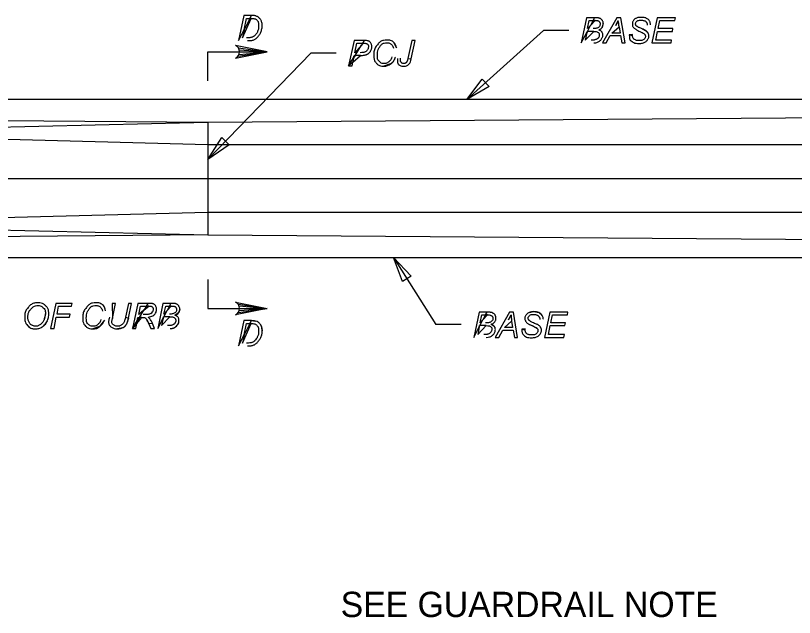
# Model space of a CAD drawing. Extents: x 0 to 680, y 0 to 440.
# Drawn here: x 153 to 239.1, y 317.2 to 383.8 of the extents above; entities that cross this region are included whole.
import ezdxf

# ---------------------------------------------------------------- set-up
doc = ezdxf.new("R2010")
doc.units = 0
doc.layers.add('Default', color=7, linetype='Continuous')

msp = doc.modelspace()

# ---------------------------------------------------------------- linework, layer by layer
at = {"layer": 'Default'}
for p, q in [((217.983, 382.884), (217.844, 382.468)), ((219.368, 382.662), (219.645, 383.244)), ((202.881, 374.488), (211.36, 382.136)), ((214.159, 382.136), (211.36, 382.136)), ((222.278, 382.302), (222.693, 382.081)), ((222.693, 382.081), (222.943, 381.831)), ((177.61, 380.224), (180.796, 379.781)), ((177.72, 380.002), (180.796, 379.781)), ((194.79, 380.834), (195.094, 380.196)), ((174.229, 379.781), (180.796, 379.781)), ((174.229, 376.566), (174.229, 379.781)), ((174.229, 367.865), (185.618, 379.614)), ((177.582, 379.282), (180.796, 379.781)), ((177.693, 379.476), (180.796, 379.781)), ((177.748, 379.781), (180.796, 379.781)), ((188.416, 379.614), (185.618, 379.614)), ((194.457, 378.423), (193.709, 378.173)), ((194.762, 357.031), (199.473, 349.605)), ((174.229, 354.592), (174.229, 351.378)), ((177.582, 351.877), (180.796, 351.378)), ((177.693, 351.683), (180.796, 351.378)), ((156.273, 350.796), (156.162, 350.27)), ((168.105, 351.018), (167.911, 350.824)), ((170.987, 350.907), (170.599, 350.63)), ((171.125, 351.323), (170.987, 350.907)), ((174.229, 351.378), (180.796, 351.378)), ((177.61, 350.935), (180.796, 351.378)), ((177.72, 351.156), (180.796, 351.378)), ((177.748, 351.378), (180.796, 351.378)), ((209.781, 350.962), (210.307, 351.046)), ((210.307, 351.046), (210.861, 350.935)), ((210.861, 350.935), (211.221, 350.63)), ((156.467, 350.02), (156.162, 349.577)), ((162.785, 350.103), (162.258, 349.383)), ((165.473, 350.325), (165.251, 349.66)), ((167.468, 350.187), (167.717, 349.688)), ((179.05, 350.048), (179.522, 349.993)), ((207.481, 350.131), (207.785, 350.685)), ((154.527, 349.3), (154.112, 349.743)), ((162.258, 349.383), (161.51, 349.134)), ((164.835, 349.272), (164.253, 349.134)), ((170.904, 349.632), (170.571, 349.3)), ((180.159, 349.411), (180.242, 348.912)), ((202.271, 349.605), (199.473, 349.605)), ((205.596, 349.66), (205.929, 349.438)), ((210.141, 349.466), (210.667, 349.189)), ((205.596, 348.829), (205.402, 348.635)), ((179.522, 347.942), (179.3, 347.72))]:
    msp.add_line(p, q, dxfattribs=at)
for points in [[(178.895, 383.466), (179.05, 383.771), (178.219, 383.771), (177.637, 381), (178.247, 382.196), (178.524, 383.466)], [(178.895, 383.466), (178.247, 382.196), (178.053, 381.305), (179.023, 383.466)], [(216.22, 382.025), (216.569, 382.684), (216.237, 382.33), (216.431, 383.217), (216.851, 383.217), (217.013, 383.521), (216.126, 383.521), (215.544, 380.75), (216.158, 381.909), (216.182, 382.025)], [(217.9, 380.75), (218.315, 380.75), (218.759, 381.554), (219.895, 381.554), (220.033, 380.75), (220.393, 380.75), (219.922, 383.521), (219.479, 383.521)], [(223.358, 380.75), (225.492, 380.75), (225.547, 381.055), (223.802, 381.055), (223.996, 382.025), (225.631, 382.025), (225.686, 382.358), (224.051, 382.358), (224.245, 383.217), (225.908, 383.217), (225.963, 383.521), (223.94, 383.521)], [(216.569, 382.684), (217.068, 383.217), (216.851, 383.217)], [(216.22, 382.025), (216.158, 381.909), (215.988, 381.055), (216.93, 382.025)], [(190.522, 379.365), (191.25, 380.514), (190.495, 379.67), (190.716, 380.723), (191.382, 380.723), (191.575, 381.028), (190.411, 381.028), (189.802, 378.229), (190.362, 379.113), (190.411, 379.365)], [(196.729, 378.977), (197.173, 381.028), (196.785, 381.028), (196.369, 379.032)], [(221.225, 381.582), (221.225, 381.693), (220.864, 381.637)], [(191.25, 380.514), (191.437, 380.723), (191.382, 380.723)], [(190.267, 378.626), (191.132, 379.365), (190.522, 379.365), (190.362, 379.113)], [(189.802, 378.229), (190.19, 378.229), (190.267, 378.626)], [(205.347, 375.929), (202.881, 374.488), (204.599, 376.76)], [(124.351, 372.41), (174.229, 371.994), (174.229, 359.525), (124.351, 359.109)], [(176.584, 369.5), (174.229, 367.865), (175.781, 370.276)], [(195.787, 354.371), (194.762, 357.031), (196.729, 354.953)], [(156.827, 349.189), (157.215, 349.189), (157.465, 350.436), (158.933, 350.436), (159.016, 350.768), (157.548, 350.768), (157.714, 351.655), (159.155, 351.655), (159.238, 351.96), (157.409, 351.96)], [(163.672, 350.27), (164.032, 351.96), (163.644, 351.96)], [(165.473, 350.325), (165.805, 351.96), (165.445, 351.96), (165.112, 350.436)], [(166.656, 350.408), (167.157, 351.202), (166.581, 350.713), (166.775, 351.655), (167.442, 351.655), (167.634, 351.96), (166.47, 351.96), (165.888, 349.189), (166.422, 350.036), (166.498, 350.408)], [(167.157, 351.202), (167.689, 351.655), (167.442, 351.655)], [(169.363, 350.464), (169.727, 351.152), (169.38, 350.768), (169.574, 351.655), (169.994, 351.655), (170.156, 351.96), (169.269, 351.96), (168.687, 349.189), (169.295, 350.337), (169.324, 350.464)], [(169.727, 351.152), (170.183, 351.655), (169.994, 351.655)], [(204.34, 349.494), (204.669, 350.121), (204.377, 349.799), (204.543, 350.685), (204.965, 350.685), (205.125, 350.99), (204.239, 350.99), (203.657, 348.191), (204.266, 349.352), (204.294, 349.494)], [(206.012, 348.191), (206.428, 348.191), (206.871, 348.995), (208.007, 348.995), (208.146, 348.191), (208.506, 348.191), (208.035, 350.99), (207.592, 350.99)], [(211.471, 348.191), (213.605, 348.191), (213.688, 348.524), (211.914, 348.524), (212.108, 349.494), (213.743, 349.494), (213.798, 349.799), (212.191, 349.799), (212.358, 350.685), (214.02, 350.685), (214.076, 350.99), (212.053, 350.99)], [(166.36, 349.736), (166.941, 350.408), (166.656, 350.408), (166.422, 350.036)], [(169.363, 350.464), (169.295, 350.337), (169.103, 349.494), (170.045, 350.464)], [(178.883, 349.716), (179.05, 350.048), (178.219, 350.048), (177.637, 347.249), (178.252, 348.466), (178.524, 349.716)], [(204.669, 350.121), (205.181, 350.685), (204.965, 350.685)], [(207.841, 349.993), (207.952, 349.3), (207.037, 349.3)], [(165.888, 349.189), (166.249, 349.189), (166.36, 349.736)], [(167.717, 349.688), (167.911, 349.189), (168.327, 349.189), (168.105, 349.716)], [(178.883, 349.716), (178.252, 348.466), (178.053, 347.554), (179.023, 349.716)], [(204.34, 349.494), (204.266, 349.352), (204.1, 348.524), (205.042, 349.494)], [(209.337, 349.05), (209.337, 349.134), (208.977, 349.106)]]:
    msp.add_lwpolyline(points, close=True, dxfattribs=at)
for points in [[(219.728, 382.524), (219.839, 381.831), (218.925, 381.831), (219.728, 382.524), (219.645, 383.244)], [(177.277, 379.06), (180.796, 379.781), (177.277, 380.473)], [(174.229, 371.994), (287.285, 372.825), (453.432, 379.06)], [(104.428, 374.488), (104.428, 372.41), (104.428, 359.109), (104.428, 357.031), (254.033, 357.031), (254.033, 374.488), (104.428, 374.488)], [(287.285, 369.5), (174.229, 369.5), (124.351, 370.803), (174.229, 371.994)], [(104.428, 365.759), (254.033, 365.759), (634.239, 365.759)], [(287.285, 362.019), (174.229, 362.019), (124.351, 360.716), (174.229, 359.525)], [(174.229, 359.525), (287.285, 358.693), (453.432, 352.459)], [(177.277, 352.099), (180.796, 351.378), (177.277, 350.685)]]:
    msp.add_lwpolyline(points, dxfattribs=at)
for centre, radius, start, end in [((217.302, 382.88), 0.681, 322.78993, 0.34017), ((217.099, 384.1), 2.686, 327.64547, 341.42784), ((201.544, 380.791), 18.267, 5.4445, 7.71939), ((221.271, 379.914), 2.592, 56.71344, 67.14158), ((222.454, 381.592), 0.544, 26.07536, 63.92464), ((176.983, 379.767), 0.765, 292.60579, 67.39421), ((194.036, 380.082), 1.064, 6.17339, 44.94654), ((193.719, 379.389), 1.216, 269.5103, 307.35959), ((176.983, 351.392), 0.765, 292.60579, 67.39421), ((154.988, 350.792), 1.285, 336.02844, 0.19425), ((167.561, 351.368), 0.647, 302.76899, 327.23101), ((170.333, 351.412), 0.826, 288.76677, 322.30859), ((170.445, 351.319), 0.681, 322.78993, 0.34017), ((210.292, 349.432), 1.613, 89.46445, 108.48081), ((210.294, 349.538), 1.507, 67.88483, 89.4953), ((210.413, 350.04), 1.001, 36.12511, 63.40217), ((155.195, 350.569), 1.386, 314.29656, 336.6864), ((161.298, 350.637), 1.58, 307.43755, 340.24608), ((162.866, 350.824), 2.654, 333.97562, 349.15449), ((163.872, 348.077), 4.168, 22.72973, 30.40037), ((179.055, 348.058), 1.99, 76.44444, 90.13588), ((202.332, 353.324), 6.058, 328.1968, 334.18162), ((155.229, 350.374), 1.283, 209.44926, 236.85552), ((161.521, 350.349), 1.216, 269.5103, 307.35959), ((164.254, 350.422), 1.288, 269.96588, 296.81912), ((170.083, 350.121), 0.955, 300.74997, 329.25003), ((178.673, 348.907), 1.569, 0.18972, 18.73492), ((205.221, 348.737), 0.996, 44.74181, 67.87806), ((209.159, 346.963), 2.689, 55.88942, 68.5935), ((205.052, 349.179), 0.647, 302.76899, 327.23101), ((178.825, 348.417), 0.843, 304.28835, 325.71165)]:
    msp.add_arc(centre, radius, start, end, dxfattribs=at)
for points, degree in [([(179.023, 383.466), (179.189, 383.466), (179.355, 383.438), (179.438, 383.411), (179.549, 383.383), (179.66, 383.3), (179.743, 383.189), (179.826, 383.05), (179.854, 382.884), (179.854, 382.662), (179.854, 382.441), (179.826, 382.274), (179.771, 382.108), (179.715, 381.942), (179.632, 381.803), (179.522, 381.693), (179.466, 381.582), (179.383, 381.526), (179.3, 381.471), (179.217, 381.415), (179.134, 381.388), (179.05, 381.36), (178.884, 381.332), (178.718, 381.305), (178.496, 381.305)], 3), ([(178.635, 381), (178.801, 381), (178.967, 381), (179.106, 381.028), (179.244, 381.055), (179.411, 381.138), (179.522, 381.194), (179.632, 381.277), (179.743, 381.388), (179.854, 381.526), (179.965, 381.665), (180.076, 381.831), (180.131, 382.025), (180.187, 382.219), (180.242, 382.413), (180.242, 382.635), (180.242, 382.829), (180.214, 382.995), (180.159, 383.133), (180.103, 383.3), (180.02, 383.411), (179.909, 383.521), (179.799, 383.632), (179.66, 383.688), (179.522, 383.743), (179.411, 383.771), (179.244, 383.771), (179.05, 383.771)], 3), ([(217.983, 382.884), (217.983, 382.995), (217.955, 383.078), (217.9, 383.189), (217.872, 383.272), (217.789, 383.355), (217.706, 383.411), (217.622, 383.466), (217.512, 383.494), (217.373, 383.521), (217.29, 383.521), (217.179, 383.521), (217.013, 383.521)], 3), ([(223.192, 382.746), (223.192, 382.773), (223.192, 382.801), (223.192, 382.801), (223.192, 382.912), (223.164, 383.05), (223.109, 383.161), (223.026, 383.3), (222.915, 383.383), (222.749, 383.466), (222.61, 383.549), (222.416, 383.577), (222.195, 383.577), (222.001, 383.577), (221.807, 383.549), (221.668, 383.494), (221.53, 383.438), (221.391, 383.355), (221.336, 383.217), (221.252, 383.106), (221.197, 382.967), (221.197, 382.829), (221.197, 382.718), (221.225, 382.607), (221.28, 382.496), (221.363, 382.413), (221.446, 382.33), (221.585, 382.247), (221.64, 382.191), (221.807, 382.108), (222.028, 382.025), (222.305, 381.887), (222.472, 381.803), (222.555, 381.72), (222.61, 381.665), (222.638, 381.582), (222.638, 381.499), (222.638, 381.36), (222.582, 381.249), (222.472, 381.138), (222.333, 381.055), (222.167, 381), (221.945, 381), (221.779, 381), (221.668, 381.028), (221.53, 381.083), (221.419, 381.138), (221.336, 381.194), (221.28, 381.277), (221.252, 381.388), (221.225, 381.471), (221.225, 381.582)], 3), ([(217.068, 383.217), (217.235, 383.217), (217.345, 383.217), (217.428, 383.189), (217.484, 383.161), (217.539, 383.106), (217.567, 383.05), (217.622, 382.995), (217.622, 382.939), (217.622, 382.856), (217.622, 382.69), (217.567, 382.552), (217.456, 382.468), (217.345, 382.385), (217.124, 382.33), (216.847, 382.33)], 3), ([(222.278, 382.302), (222.028, 382.413), (221.862, 382.468), (221.807, 382.524), (221.723, 382.579), (221.64, 382.607), (221.613, 382.662), (221.585, 382.718), (221.557, 382.801), (221.557, 382.856), (221.557, 382.967), (221.613, 383.078), (221.696, 383.133), (221.807, 383.217), (221.973, 383.272), (222.167, 383.272), (222.278, 383.272), (222.389, 383.244), (222.472, 383.217), (222.582, 383.189), (222.638, 383.161), (222.693, 383.106), (222.749, 383.05), (222.804, 382.967), (222.832, 382.912), (222.832, 382.856), (222.832, 382.801), (222.832, 382.718)], 3), ([(216.93, 382.025), (217.179, 382.025), (217.318, 381.997), (217.401, 381.914), (217.484, 381.859), (217.539, 381.748), (217.539, 381.637), (217.539, 381.526), (217.512, 381.443), (217.484, 381.36), (217.428, 381.305), (217.373, 381.221), (217.29, 381.194), (217.207, 381.138), (217.124, 381.111), (216.985, 381.083), (216.93, 381.055), (216.819, 381.055), (216.653, 381.055)], 3), ([(216.93, 380.75), (217.124, 380.75), (217.29, 380.778), (217.428, 380.861), (217.567, 380.944), (217.706, 381.055), (217.789, 381.194), (217.872, 381.332), (217.927, 381.471), (217.927, 381.637), (217.927, 381.748), (217.872, 381.887), (217.816, 381.97), (217.733, 382.08), (217.622, 382.136), (217.456, 382.191), (217.65, 382.247), (217.761, 382.358), (217.844, 382.468)], 3), ([(220.864, 381.637), (220.864, 381.277), (220.948, 381.028), (221.169, 380.889), (221.363, 380.778), (221.613, 380.695), (221.945, 380.695), (222.139, 380.695), (222.333, 380.723), (222.499, 380.806), (222.666, 380.861), (222.776, 380.972), (222.887, 381.083), (222.97, 381.222), (223.026, 381.36), (223.026, 381.526), (223.026, 381.637), (222.998, 381.748), (222.943, 381.831)], 3), ([(191.132, 379.365), (191.298, 379.365), (191.492, 379.393), (191.658, 379.42), (191.742, 379.448), (191.825, 379.476), (191.908, 379.503), (191.963, 379.559), (192.046, 379.614), (192.129, 379.697), (192.185, 379.753), (192.24, 379.864), (192.296, 379.975), (192.351, 380.113), (192.379, 380.224), (192.379, 380.335), (192.379, 380.473), (192.323, 380.612), (192.268, 380.723), (192.213, 380.834), (192.129, 380.917), (192.019, 380.944), (191.908, 381), (191.769, 381.028), (191.575, 381.028)], 3), ([(194.79, 380.834), (194.596, 381), (194.346, 381.055), (194.069, 381.055), (193.654, 381.055), (193.321, 380.917), (193.072, 380.64), (192.767, 380.307), (192.601, 379.891), (192.601, 379.393), (192.601, 379.005), (192.711, 378.7), (192.905, 378.478), (193.099, 378.284), (193.376, 378.173), (193.709, 378.173)], 3), ([(191.437, 380.723), (191.603, 380.723), (191.742, 380.695), (191.797, 380.667), (191.852, 380.64), (191.908, 380.612), (191.936, 380.556), (191.991, 380.501), (191.991, 380.418), (191.991, 380.335), (191.991, 380.196), (191.963, 380.085), (191.908, 380.002), (191.825, 379.891), (191.742, 379.808), (191.631, 379.753), (191.52, 379.697), (191.354, 379.67), (191.104, 379.67)], 3), ([(194.596, 379.199), (194.54, 378.977), (194.429, 378.811), (194.263, 378.672), (194.097, 378.561), (193.931, 378.478), (193.737, 378.478), (193.515, 378.478), (193.321, 378.561), (193.182, 378.728), (193.044, 378.866), (192.988, 379.088), (192.988, 379.365), (192.988, 379.725), (193.072, 380.03), (193.238, 380.307), (193.46, 380.612), (193.737, 380.75), (194.069, 380.75), (194.263, 380.75), (194.402, 380.695), (194.513, 380.612), (194.651, 380.501), (194.706, 380.362), (194.762, 380.169)], 3), ([(194.457, 378.423), (194.679, 378.589), (194.873, 378.838), (194.984, 379.171)], 2), ([(195.233, 379.032), (195.205, 378.949), (195.205, 378.866), (195.205, 378.783), (195.205, 378.589), (195.261, 378.451), (195.372, 378.34), (195.482, 378.229), (195.676, 378.173), (195.898, 378.173), (196.12, 378.173), (196.286, 378.229), (196.452, 378.367), (196.591, 378.478), (196.674, 378.7), (196.729, 378.977)], 3), ([(196.369, 379.032), (196.341, 378.894), (196.314, 378.783), (196.286, 378.728), (196.231, 378.644), (196.203, 378.589), (196.12, 378.534), (196.064, 378.506), (195.981, 378.478), (195.898, 378.478), (195.787, 378.478), (195.704, 378.506), (195.649, 378.589), (195.565, 378.644), (195.538, 378.728), (195.538, 378.838), (195.538, 378.866), (195.565, 378.949), (195.565, 379.06)], 3), ([(156.467, 350.02), (156.578, 350.242), (156.633, 350.491), (156.633, 350.768), (156.633, 351.156), (156.522, 351.461), (156.301, 351.683), (156.079, 351.905), (155.802, 352.015), (155.469, 352.015), (155.054, 352.015), (154.694, 351.877), (154.416, 351.572), (154.112, 351.24), (153.973, 350.852), (153.973, 350.353), (153.973, 350.131), (154.029, 349.937), (154.112, 349.743)], 3), ([(156.162, 350.27), (156.107, 350.103), (156.024, 349.937), (155.941, 349.826), (155.83, 349.715), (155.719, 349.605), (155.58, 349.549), (155.442, 349.466), (155.331, 349.438), (155.165, 349.438), (155.026, 349.438), (154.888, 349.494), (154.749, 349.549), (154.61, 349.632), (154.527, 349.743), (154.444, 349.882), (154.389, 350.02), (154.333, 350.159), (154.333, 350.325), (154.333, 350.741), (154.444, 351.101), (154.694, 351.35), (154.915, 351.6), (155.165, 351.711), (155.442, 351.711), (155.691, 351.711), (155.885, 351.627), (156.024, 351.461), (156.19, 351.295), (156.273, 351.073), (156.273, 350.796)], 3), ([(162.896, 351.129), (162.868, 351.406), (162.757, 351.627), (162.591, 351.794), (162.397, 351.932), (162.175, 352.015), (161.87, 352.015), (161.455, 352.015), (161.122, 351.877), (160.873, 351.572), (160.568, 351.24), (160.402, 350.824), (160.402, 350.325), (160.402, 349.937), (160.513, 349.66), (160.707, 349.438), (160.901, 349.244), (161.178, 349.134), (161.51, 349.134)], 3), ([(162.397, 350.159), (162.341, 349.937), (162.231, 349.743), (162.064, 349.632), (161.926, 349.494), (161.732, 349.438), (161.538, 349.438), (161.316, 349.438), (161.122, 349.522), (160.984, 349.66), (160.845, 349.826), (160.79, 350.048), (160.79, 350.325), (160.79, 350.685), (160.873, 350.99), (161.067, 351.267), (161.261, 351.572), (161.538, 351.711), (161.898, 351.711), (162.064, 351.711), (162.203, 351.655), (162.341, 351.572), (162.452, 351.461), (162.508, 351.323), (162.563, 351.101)], 3), ([(168.105, 349.716), (168.05, 349.882), (167.939, 350.048), (167.828, 350.214), (167.773, 350.297), (167.689, 350.353), (167.606, 350.436), (167.939, 350.491), (168.161, 350.575), (168.327, 350.741), (168.465, 350.879), (168.548, 351.073), (168.548, 351.295), (168.548, 351.461), (168.493, 351.6), (168.438, 351.711), (168.382, 351.794), (168.271, 351.877), (168.161, 351.905), (168.05, 351.96), (167.856, 351.96), (167.634, 351.96)], 3), ([(167.689, 351.655), (167.828, 351.655), (167.911, 351.655), (167.994, 351.627), (168.05, 351.6), (168.077, 351.572), (168.133, 351.517), (168.161, 351.461), (168.188, 351.378), (168.188, 351.295), (168.188, 351.212), (168.161, 351.101), (168.105, 351.018)], 3), ([(170.183, 351.655), (170.377, 351.655), (170.488, 351.655), (170.544, 351.627), (170.627, 351.6), (170.682, 351.544), (170.71, 351.489), (170.738, 351.434), (170.765, 351.378), (170.765, 351.295), (170.765, 351.129), (170.71, 350.99), (170.599, 350.907), (170.46, 350.824), (170.266, 350.768), (169.989, 350.768)], 3), ([(171.125, 351.323), (171.125, 351.434), (171.098, 351.517), (171.042, 351.627), (170.987, 351.711), (170.931, 351.794), (170.848, 351.849), (170.738, 351.905), (170.654, 351.932), (170.516, 351.96), (170.433, 351.96), (170.322, 351.96), (170.156, 351.96)], 3), ([(167.911, 350.824), (167.8, 350.768), (167.689, 350.741), (167.551, 350.741), (167.468, 350.713), (167.329, 350.713), (167.08, 350.713)], 3), ([(205.596, 349.66), (205.763, 349.715), (205.901, 349.799), (205.984, 349.937), (206.067, 350.048), (206.095, 350.187), (206.095, 350.325), (206.095, 350.436), (206.067, 350.547), (206.04, 350.63), (205.984, 350.741), (205.901, 350.796), (205.818, 350.852), (205.735, 350.907), (205.624, 350.962), (205.486, 350.962), (205.43, 350.99), (205.292, 350.99), (205.125, 350.99)], 3), ([(208.977, 349.106), (208.977, 348.746), (209.088, 348.496), (209.282, 348.358), (209.476, 348.219), (209.725, 348.164), (210.058, 348.164), (210.252, 348.164), (210.446, 348.191), (210.612, 348.247), (210.778, 348.33), (210.889, 348.441), (211, 348.552), (211.083, 348.69), (211.138, 348.829), (211.138, 348.967), (211.138, 349.106), (211.111, 349.217), (211.055, 349.3), (211, 349.383), (210.917, 349.466), (210.806, 349.549), (210.75, 349.605), (210.612, 349.66), (210.39, 349.743), (210.141, 349.854), (210.002, 349.937), (209.919, 349.965), (209.836, 350.02), (209.781, 350.076), (209.725, 350.131), (209.697, 350.187), (209.67, 350.242), (209.67, 350.325), (209.67, 350.436), (209.725, 350.519), (209.808, 350.602), (209.919, 350.685), (210.085, 350.741), (210.279, 350.741), (210.39, 350.741), (210.501, 350.713), (210.612, 350.685), (210.695, 350.658), (210.778, 350.602), (210.806, 350.547), (210.861, 350.491), (210.917, 350.436), (210.944, 350.353), (210.944, 350.325), (210.972, 350.242), (210.972, 350.187)], 3), ([(209.781, 350.962), (209.642, 350.879), (209.531, 350.796), (209.448, 350.685), (209.365, 350.574), (209.31, 350.436), (209.31, 350.297), (209.31, 350.159), (209.365, 350.048), (209.42, 349.965), (209.476, 349.854), (209.559, 349.771), (209.697, 349.688), (209.781, 349.632), (209.919, 349.577), (210.141, 349.466)], 3), ([(163.339, 350.436), (163.284, 350.214), (163.256, 350.048), (163.256, 349.937), (163.256, 349.799), (163.284, 349.66), (163.367, 349.522), (163.45, 349.411), (163.561, 349.3), (163.699, 349.244), (163.866, 349.161), (164.059, 349.134), (164.253, 349.134)], 3), ([(165.112, 350.436), (165.057, 350.159), (165.002, 349.965), (164.918, 349.826), (164.863, 349.716), (164.752, 349.605), (164.641, 349.549), (164.503, 349.466), (164.392, 349.438), (164.253, 349.438), (164.059, 349.438), (163.921, 349.494), (163.782, 349.577), (163.672, 349.66), (163.616, 349.799), (163.616, 349.937), (163.616, 350.02), (163.644, 350.103), (163.672, 350.27)], 3), ([(166.941, 350.408), (167.08, 350.408), (167.191, 350.408), (167.274, 350.381), (167.329, 350.353), (167.385, 350.297), (167.468, 350.187)], 3), ([(170.045, 350.464), (170.294, 350.464), (170.46, 350.436), (170.544, 350.353), (170.627, 350.297), (170.682, 350.187), (170.682, 350.076), (170.682, 349.965), (170.654, 349.882), (170.599, 349.799), (170.571, 349.743), (170.516, 349.66), (170.433, 349.632), (170.35, 349.577), (170.239, 349.522), (170.128, 349.522), (170.072, 349.494), (169.962, 349.494), (169.768, 349.494)], 3), ([(170.904, 349.632), (171.015, 349.771), (171.042, 349.909), (171.042, 350.076), (171.042, 350.187), (171.015, 350.325), (170.931, 350.408), (170.876, 350.519), (170.738, 350.575), (170.599, 350.63)], 3), ([(180.159, 349.411), (180.103, 349.549), (180.02, 349.688), (179.909, 349.799), (179.799, 349.882), (179.66, 349.965), (179.522, 349.993)], 3), ([(205.181, 350.685), (205.347, 350.685), (205.486, 350.658), (205.541, 350.63), (205.596, 350.602), (205.652, 350.574), (205.707, 350.519), (205.735, 350.464), (205.763, 350.381), (205.763, 350.297), (205.763, 350.131), (205.68, 350.02), (205.569, 349.937), (205.458, 349.854), (205.236, 349.799), (204.959, 349.799)], 3), ([(207.785, 350.685), (207.785, 350.491), (207.813, 350.27), (207.841, 349.993)], 2), ([(211.305, 350.214), (211.332, 350.242), (211.332, 350.242), (211.332, 350.27), (211.332, 350.381), (211.277, 350.491), (211.221, 350.63)], 3), ([(154.527, 349.3), (154.721, 349.189), (154.915, 349.134), (155.137, 349.134), (155.359, 349.134), (155.553, 349.189), (155.747, 349.272), (155.885, 349.328), (156.024, 349.438), (156.162, 349.577)], 3), ([(164.835, 349.272), (165.029, 349.383), (165.14, 349.522), (165.251, 349.66)], 2), ([(170.072, 349.189), (170.239, 349.189), (170.405, 349.217), (170.571, 349.3)], 2), ([(179.023, 349.716), (179.189, 349.716), (179.355, 349.716), (179.438, 349.688), (179.549, 349.632), (179.66, 349.549), (179.743, 349.438), (179.826, 349.328), (179.854, 349.134), (179.854, 348.912), (179.854, 348.718), (179.826, 348.524), (179.771, 348.385), (179.715, 348.219), (179.632, 348.081), (179.522, 347.942)], 3), ([(205.042, 349.494), (205.292, 349.494), (205.458, 349.438), (205.541, 349.383), (205.624, 349.3), (205.652, 349.217), (205.652, 349.078), (205.652, 348.995), (205.624, 348.912), (205.596, 348.829)], 3), ([(205.042, 348.191), (205.236, 348.191), (205.402, 348.247), (205.541, 348.302), (205.68, 348.385), (205.818, 348.496), (205.901, 348.635), (205.984, 348.773), (206.04, 348.94), (206.04, 349.078), (206.04, 349.217), (206.012, 349.328), (205.929, 349.438)], 3), ([(210.667, 349.189), (210.723, 349.106), (210.75, 349.023), (210.75, 348.94), (210.75, 348.829), (210.695, 348.718), (210.584, 348.607), (210.473, 348.524), (210.279, 348.469), (210.058, 348.469), (209.919, 348.469), (209.781, 348.496), (209.67, 348.524), (209.531, 348.579), (209.448, 348.663), (209.42, 348.746), (209.365, 348.829), (209.337, 348.94), (209.337, 349.05)], 3), ([(178.635, 347.249), (178.801, 347.249), (178.967, 347.249), (179.106, 347.305), (179.244, 347.332), (179.411, 347.388), (179.522, 347.471), (179.632, 347.554), (179.743, 347.665), (179.854, 347.804), (179.965, 347.942), (180.076, 348.108), (180.131, 348.275), (180.187, 348.469), (180.242, 348.663), (180.242, 348.912)], 3), ([(205.402, 348.635), (205.347, 348.579), (205.236, 348.552), (205.125, 348.524), (205.042, 348.524), (204.931, 348.524), (204.765, 348.524)], 3), ([(179.3, 347.72), (179.217, 347.665), (179.134, 347.637), (179.05, 347.61), (178.884, 347.582), (178.718, 347.554), (178.496, 347.554)], 3)]:
    msp.add_open_spline(points, degree=degree, dxfattribs=at)

# ---------------------------------------------------------------- texts
msp.add_text('SEE GUARDRAIL NOTE', height=2.79314, dxfattribs=at).set_placement((188.926, 317.282))

doc.saveas('drawing.dxf')
